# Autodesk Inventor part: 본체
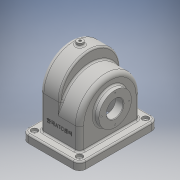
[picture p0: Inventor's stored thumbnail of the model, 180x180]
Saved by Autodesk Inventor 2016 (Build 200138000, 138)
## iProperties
Created: 2017-11
Part Number: 본체
Material: 일반
Document SubType Name: Modeling
Designer: USER
Density: 1 g/cm^3
Appearance: 기본값
Author: USER
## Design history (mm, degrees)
sketch "스케치1"
  geometry: L1 (-58, 0)-(-58, -80); L2 (58, 0)-(58, -80); L3 (58, -80)-(-58, -80); L4 (53, 0)-(53, -75); L5 (53, -75)-(-53, -75); L6 (-53, -75)-(-53, 0); A1 r 58 centre (0, 0) between (58, 0) and (-58, 0); A2 r 53 centre (0, 0) between (53, 0) and (-53, 0); 1 further point
  constraints: 12 end point, 4 point on circle, 2 centre point, 2 tangent, 2 vertical, 1 coincident, 3 other
  dimensions: "d0" = 116 diameter of A1; "d1" = 80 distance of L1.start L1.end; "d2" = 80 distance of L2.start L2.end; "d10" = 5 radial gap between concentric circles of A1 A2
node "작업 평면1"
extrude "돌출3" join sketch "스케치1" distance "d11" = 38; taper "d12" = 0 deg
sketch "스케치3"
  geometry: L1 (0, -58)-(80, -58) reference; L2 (0, -58)-(80, -58); L3 (80, 58)-(0, 58); L4 (80, 58)-(80, -58) reference; L5 (80, -58)-(80, 58); A1 r 58 centre (0, 0) between (0, 58) and (0, -58) reference; A2 r 58 centre (0, 0) between (0, 58) and (0, -58)
  constraints: 6 end point, 2 equal length, 2 point on circle, 2 point on line, 1 centre point, 1 coincident, 1 vertical
  dimensions: "d13" = 116 diameter of A2
extrude "돌출4" join sketch "스케치3" distance "d14" = 5; taper "d15" = 0 deg
sketch "스케치4"
  geometry: L1 (0, 58)-(-80, 58) reference; L2 (-80, 58)-(0, 58) reference; L3 (0, 58)-(-80, 58); L4 (0, -58)-(-80, -58) reference; L5 (-80, 58)-(-80, -58); L6 (-80, -58)-(0, -58); A1 r 58 centre (0, 0) between (0, -58) and (0, 58) reference; A2 r 58 centre (0, 0) between (0, -58) and (0, 58)
  constraints: 6 end point, 2 perpendicular, 2 point on circle, 2 point on line, 1 centre point, 1 coincident, 1 collinear
  dimensions: "d16" = 116 diameter of A2
extrude "돌출5" join sketch "스케치4" distance "d17" = 5; taper "d18" = 0 deg
sketch "스케치5"
  geometry: L1 (80, -58)-(80, 58) reference; L2 (80, -58)-(0, -58) reference; L3 (23, -58)-(80, -58); L4 (80, 58)-(80, -58) reference; L5 (80, -58)-(80, 58); L6 (80, 58)-(23, 58); L7 (0, 58)-(80, 58) reference; L8 (23, -53)-(75, -53); L9 (75, -53)-(75, 53); L10 (75, 53)-(23, 53); A1 r 58 centre (23, 0) between (23, 58) and (23, -58); A2 r 53 centre (23, 0) between (23, 53) and (23, -53)
  constraints: 12 end point, 4 point on circle, 2 centre point, 2 perpendicular, 2 point on line, 1 collinear, 1 tangent, 3 other
  dimensions: "d20" = 57 distance from line of A1.centre L1; "d21" = 58 radius of A1; "d22" = 5 radial gap between concentric circles of A1 A2
extrude "돌출6" join sketch "스케치5" distance "d23" = 38; taper "d24" = 0 deg
sketch "스케치6"
  geometry: L1 (23, -53)-(75, -53) reference; L2 (75, -53)-(75, 53) reference; L3 (75, 53)-(23, 53) reference; L4 (80, -58)-(0, -58) reference; L5 (0, 58)-(80, 58) reference; L6 (80, 58)-(80, -58) reference; L7 (80, -58)-(0, -58) reference; L8 (23, -58)-(80, -58); L9 (80, 58)-(23, 58); L10 (0, 58)-(80, 58) reference; L11 (80, 58)-(80, -58) reference; L12 (80, -58)-(80, 58); L13 (23, 53)-(75, 53); L14 (75, 53)-(75, -53); L15 (75, -53)-(23, -53); A1 r 53 centre (23, 0) between (23, 53) and (23, -53) reference; A2 r 58 centre (23, 0) between (23, 58) and (23, -58); A3 r 58 centre (0, 0) between (0, 58) and (0, -58) reference; A4 r 53 centre (23, 0) between (23, 53) and (23, -53); 1 further point
  constraints: 12 end point, 4 point on circle, 2 centre point, 2 point on line, 1 coincident, 1 collinear, 1 vertical, 3 other
  dimensions: "d25" = 116 diameter of A2; "d26" = 5 radial gap between concentric circles of A2 A4
extrude "돌출7" cut sketch "스케치6" distance "d27" = 5; taper "d28" = 0 deg
sketch "스케치7"
  geometry: L1 (80, -58)-(80, 58) reference; L2 (80, 58)-(23, 58) reference; L3 (0, -58)-(23, -58) reference; L4 (80, -58)-(0, -58) reference; L5 (23, -58)-(80, -58); L6 (80, -58)-(80, 58); L7 (23, 58)-(80, 58); A1 r 58 centre (23, 0) between (23, 58) and (23, -58) reference; A2 r 58 centre (23, 0) between (23, 58) and (23, -58); 1 further point
  constraints: 6 end point, 2 point on circle, 2 point on line, 1 centre point, 1 coincident, 1 collinear, 1 horizontal, 1 perpendicular
  dimensions: "d29" = 116 diameter of A2
extrude "돌출8" join sketch "스케치7" distance "d30" = 5; taper "d31" = 0 deg
sketch "스케치8"
  geometry: L1 (17, -17)-(-93, -17); L2 (-93, -17)-(-93, 133); L3 (-93, 133)-(17, 133); L4 (17, 133)-(17, -17); L5 (-5, 5)-(-71, 5); L6 (-71, 5)-(-71, 111); L7 (-71, 111)-(-5, 111); L8 (-5, 111)-(-5, 5); L9 (0, 116)-(0, 0) reference; L10 (0, 0)-(-76, 0) reference; L11 (-76, 0)-(-76, 116) reference; L12 (0, 116)-(-76, 116) reference; 10 further points
  constraints: 16 end point, 10 midpoint, 3 horizontal alignment, 3 vertical alignment, 2 parallel, 1 horizontal, 1 perpendicular
  dimensions: "d32" = 110 distance of L1.start L1.end; "d33" = 150 distance of L3.end L1.start; "d35" = 5 distance between parallel lines of L8 L9; "d36" = 5 distance between parallel lines of L10 L5
extrude "돌출9" join sketch "스케치8" distance "d37" = 15; taper "d38" = 0 deg
sketch "스케치9"
  geometry: L1 (88, 22)-(22, 22) reference; L2 (22, 22)-(22, 128) reference; L3 (88, 128)-(88, 22) reference; L4 (88, 128)-(22, 128) reference; L5 (22, 22)-(88, 22); L6 (88, 22)-(88, 128); L7 (88, 128)-(22, 128); L8 (22, 128)-(22, 22); 1 further point
  constraints: 8 end point, 2 parallel, 1 horizontal, 1 perpendicular
extrude "돌출10" cut sketch "스케치9" distance "d39" = 15; taper "d40" = 0 deg
node "작업 평면5"
  node "작업 평면4"
sketch "스케치10"
  geometry: C1 r 6 at (-74, 0); 1 further point
  constraints: 1 centre point, 1 horizontal alignment
  dimensions: "d42" = 12 diameter of C1; "d43" = 19 distance of point (-93, 0) C1.centre
extrude "돌출11" join sketch "스케치10" stored distance "d44" = 15; taper "d45" = 0 deg
sketch "스케치11"
  geometry: C1 r 6 at (0, 0) reference; 2 further points
  constraints: 1 coincident
hole "구멍1" sketch "스케치11" at (0, 0) diameter "d46" = 4.459; stored, may be unused: countersink angle "d50" = 90 deg, drill point angle "d52" = 118 deg; dims "d47" = 10, "d48" = 4, "d49" = 2, "d51" = 12.8
sketch "스케치13"
  geometry: L1 (80, -75)-(80, 75) reference; C1 r 31 at (15, 0); C2 r 16 at (15, 0); 1 further point
  constraints: 2 centre point, 1 coincident, 1 horizontal alignment
  dimensions: "d54" = 62 diameter of C1; "d55" = 32 diameter of C2; "d56" = 65 distance from line of C1.centre L1
extrude "돌출12" join sketch "스케치13" distance "d57" = 10; taper "d58" = 0 deg
sketch "스케치14"
  geometry: C1 r 16 at (0, 0) reference; C2 r 16 at (0, 0); 1 further point
  constraints: 1 centre point, 1 coincident
  dimensions: "d59" = 32 diameter of C2
extrude "돌출13" cut sketch "스케치14" distance "d60" = 85; taper "d61" = 0 deg
sketch "스케치15"
  geometry: L1 (-80, 75)-(-80, -75) reference; C1 r 37.5 at (-15, 0); C2 r 16 at (-15, 0); A1 r 58 centre (0, 0) between (0, -58) and (0, 58) reference
  constraints: 2 centre point, 1 coincident, 1 horizontal alignment
  dimensions: "d62" = 75 diameter of C1; "d63" = 32 diameter of C2; "d64" = 65 distance from line of C1.centre L1
extrude "돌출14" join sketch "스케치15" distance "d65" = 9; taper "d66" = 0 deg
sketch "스케치16"
  geometry: C1 r 16 at (0, 0) reference; 2 further points
  constraints: 1 horizontal alignment
  dimensions: "d67" = 26 distance of point (-26, 0) C1.centre
hole "구멍2" sketch "스케치16" at (-26, 0) diameter "d68" = 2.459; stored, may be unused: countersink angle "d72" = 90 deg, drill point angle "d74" = 118 deg; dims "d69" = 6, "d70" = 4, "d71" = 2, "d73" = 8
sketch "스케치17"
  geometry: C1 r 16 at (0, 0) reference; 2 further points
  constraints: 1 horizontal alignment
  dimensions: "d78" = 29 distance of point (29, 0) C1.centre
hole "구멍3" sketch "스케치17" at (29, 0) diameter "d79" = 2.459; stored, may be unused: countersink angle "d83" = 90 deg, drill point angle "d85" = 118 deg; dims "d80" = 6, "d81" = 4, "d82" = 2, "d84" = 8
sketch "스케치19"
  geometry: L1 (0, -65)-(0, 0) reference; L2 (-17, -80)-(93, -80) reference; L3 (-17, -80)-(-17, -65) reference; L4 (-17, -65)-(93, -65) reference; 1 further point
  constraints: 1 other
  dimensions: "d93" = 40 distance from line of point (38, -40) L2; "d94" = 38 distance from line of point (38, -40) L1
feature "엠보싱1" sketch "스케치19" dims "d95" = 0.5, "d96" = 0
fillet "모깎기1" dims "d97" = 12
fillet "모깎기2" dims "d98" = 8
fillet "모깎기3" dims "d99" = 3
chamfer "모따기1" distance "d100" = 1; stored, may be unused: second distance "d101" = 2, angle "d102" = 45 deg
fillet "모깎기4" dims "d103" = 3
sketch "스케치20"
  geometry: A1 r 9 centre (81, -5) between (81, -14) and (90, -5) reference; A2 r 9 centre (81, 121) between (90, 121) and (81, 130) reference; A3 r 9 centre (-5, 121) between (-5, 130) and (-14, 121) reference; A4 r 9 centre (-5, -5) between (-14, -5) and (-5, -14) reference; 5 further points
  constraints: 4 coincident
hole "구멍4" sketch "스케치20" at (-5, -5), (81, -5), (81, 121), (-5, 121) diameter "d104" = 5; stored, may be unused: countersink angle "d108" = 90 deg, drill point angle "d110" = 0 deg; dims "d105" = 6, "d106" = 12, "d107" = 5, "d109" = 8
node "솔리드1"
pattern_circular "원형 패턴1" dims angle "d76" = 360 deg
pattern_circular "원형 패턴2" dims angle "d87" = 360 deg
node "투영된 루프1"
other parameters: "d5" = 116, "d19" = 116, "d41" = 144
